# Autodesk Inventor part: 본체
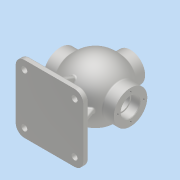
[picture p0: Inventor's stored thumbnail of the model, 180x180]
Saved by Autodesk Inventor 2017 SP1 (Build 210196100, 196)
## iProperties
Part Number: 본체
Material: 알루미늄 6061
Document SubType Name: Modeling
Designer: MRC
Density: 2.7 g/cm^3
Appearance: 알루미늄 - 평지
Mass: 1526.73 g
Surface Area: 1173.98 cm^2
Volume: 565.456 cm^3
Author: MRC
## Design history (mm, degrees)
sketch "스케치1"
  geometry: L1 (-65, 0)-(65, 0); L2 (-65, 0)-(-65, 31); L3 (-65, 31)-(-44.215, 31); L4 (65, 0)-(65, 31); L5 (65, 31)-(44.215, 31); L6 (-65, 17.5)-(-49, 17.5); L7 (-49, 17.5)-(-49, 15); L8 (-49, 15)-(-41.364, 15); L9 (65, 17.5)-(49, 17.5); L10 (49, 17.5)-(49, 15); L11 (49, 15)-(41.364, 15); A1 r 54 centre (0, 0) between (44.215, 31) and (-44.215, 31); A2 r 44 centre (0, 0) between (41.364, 15) and (-41.364, 15); 2 further points
  constraints: 22 end point, 5 perpendicular, 5 point on line, 4 point on circle, 3 coincident, 2 centre point, 2 horizontal, 2 vertical, 1 midpoint
  dimensions: "d0" = 130 distance of L1.start L1.end; "d1" = 108 diameter of A1; "d2" = 62 diameter of L5 L1; "d3" = 62 diameter of L3 L1; "d4" = 88 diameter of A2; "d5" = 35 diameter of L9 L1; "d6" = 16 distance of L9.start L9.end; "d7" = 16 distance of L6.start L6.end; "d8" = 30 diameter of L8 L1
revolve "회전1" sketch "스케치1" stored, may be unused: angle "d9" = 90 deg
chamfer "모따기1" distance "d10" = 1; stored, may be unused: second distance "d11" = 2, angle "d12" = 45 deg
chamfer "모따기2" distance "d13" = 1; stored, may be unused: second distance "d14" = 2, angle "d15" = 45 deg
fillet "모깎기1" dims "d16" = 0.6
node "작업 평면1"
sketch "스케치2"
  geometry: L1 (62.5, -62.5)-(-62.5, -62.5); L2 (-62.5, -62.5)-(-62.5, 62.5); L3 (-62.5, 62.5)-(62.5, 62.5); L4 (62.5, 62.5)-(62.5, -62.5); L5 (62.5, -62.5)-(-62.5, 62.5); L6 (-62.5, -62.5)-(62.5, 62.5); 1 further point
  constraints: 12 end point, 2 midpoint, 2 parallel, 2 perpendicular, 1 horizontal
  dimensions: "d18" = 125 distance of L2.end L3.end
sketch "스케치3"
  geometry: C1 r 31 at (0, 0) reference; 1 further point
  constraints: 1 vertical alignment
  dimensions: "d19" = 24 distance of point (0, 24) C1.centre
hole "구멍1" sketch "스케치3" at (0, 24) diameter "d20" = 3.242; stored, may be unused: countersink angle "d24" = 90 deg, drill point angle "d26" = 118 deg; dims "d21" = 12, "d22" = 4, "d23" = 2, "d25" = 15
node "작업 평면2"
sketch "스케치4"
  geometry: C1 r 27 at (0, 0); 1 further point
  constraints: 1 centre point, 1 coincident
  dimensions: "d31" = 54 diameter of C1
extrude "돌출1" join sketch "스케치4" stored distance "d32" = 10; taper "d33" = 0 deg
sketch "스케치5"
  geometry: C1 r 27 at (0, 0) reference; C2 r 13 at (0, 0)
  constraints: 1 centre point, 1 coincident
  dimensions: "d34" = 26 diameter of C2
extrude "돌출2" cut sketch "스케치5" stored distance "d35" = 0; taper "d36" = 0 deg
sketch "스케치6"
  geometry: C1 r 13 at (0, 0) reference; 1 further point
  constraints: 1 vertical alignment
  dimensions: "d37" = 20 distance of C1.centre point (0, 20)
hole "구멍2" sketch "스케치6" at (0, 20) diameter "d38" = 3.242; stored, may be unused: countersink angle "d42" = 90 deg, drill point angle "d44" = 118 deg; dims "d39" = 9, "d40" = 4, "d41" = 2, "d43" = 11
extrude "돌출3" join sketch "스케치2" distance "d48" = 10; taper "d49" = 0 deg
fillet "모깎기2" dims "d50" = 16
fillet "모깎기3" dims "d51" = 3
sketch "스케치7"
  geometry: L1 (-75, -50.5)-(-50.777, -41.684); L2 (-75, 50.5)-(-58.826, 44.613); L3 (-78, -62.5)-(-85, -62.5) reference; L4 (-75, 46.5)-(-75, -46.5) reference; L5 (-85, 62.5)-(-78, 62.5) reference; 1 further point
  constraints: 4 end point, 2 point on line
  dimensions: "d52" = 20 deg angle of L1 L3; "d53" = 12 distance from line of L1.start L3; "d54" = 20 deg angle of L2 L5; "d55" = 12 distance from line of L2.start L5
feature "리브1" dims "d56" = 30, "d57" = 8, "d58" = 0, "d59" = 0, "d60" = 1, "d61" = 1
feature "리브2" dims "d62" = 30, "d63" = 8, "d64" = 0, "d65" = 0, "d66" = 1, "d67" = 1
sketch "스케치8"
  geometry: L1 (50.5, -75)-(43.286, -55.179); L2 (-50.5, -75)-(-43.704, -56.329); L3 (62.5, -85)-(62.5, -78) reference; L4 (-62.5, -78)-(-62.5, -85) reference; L5 (46.5, -75)-(-46.5, -75) reference; 1 further point
  constraints: 4 end point, 2 point on line
  dimensions: "d68" = 12 distance from line of L1.start L3; "d69" = 20 deg angle of L3 L1; "d70" = 20 deg angle of L2 L4; "d71" = 12 distance from line of L4 L2.start
feature "리브3" dims "d72" = 30, "d73" = 8, "d74" = 0, "d75" = 0, "d76" = 1, "d77" = 1
feature "리브4" dims "d78" = 30, "d79" = 8, "d80" = 0, "d81" = 0, "d82" = 1, "d83" = 1
fillet "모깎기4" dims "d84" = 3
fillet "모깎기5" dims "d85" = 3
fillet "모깎기6" dims "d86" = 3
chamfer "모따기3" distance "d87" = 1; stored, may be unused: second distance "d88" = 2, angle "d89" = 45 deg
fillet "모깎기7" dims "d90" = 3
node "작업 평면3"
sketch "스케치9"
  geometry: L1 (-27, 65)-(27, 65) reference; 2 further points
  constraints: 1 vertical alignment, 1 other
  dimensions: "d92" = 9 distance from line of point (0, 56) L1
feature "엠보싱1" sketch "스케치9" dims "d0" = 130, "d93" = 0.5, "d94" = 0
sketch "스케치10"
  geometry: C1 r 5.5 at (-46.5, -46.5); C2 r 5.5 at (-46.5, 46.5); C3 r 5.5 at (46.5, 46.5); C4 r 5.5 at (46.5, -46.5); A1 r 13 centre (46.5, 46.5) between (59.5, 46.5) and (46.5, 59.5) reference; A2 r 13 centre (-46.5, 46.5) between (-46.5, 59.5) and (-59.5, 46.5) reference; A3 r 13 centre (-46.5, -46.5) between (-59.5, -46.5) and (-46.5, -59.5) reference; A4 r 13 centre (46.5, -46.5) between (46.5, -59.5) and (59.5, -46.5) reference; 1 further point
  constraints: 4 centre point, 4 coincident
  dimensions: "d95" = 11 diameter of C1; "d96" = 11 diameter of C2; "d97" = 11 diameter of C3; "d98" = 11 diameter of C4
extrude "돌출4" cut sketch "스케치10" stored distance "d99" = 10; taper "d100" = 0 deg
node "솔리드1"
pattern_circular "원형 패턴1" dims angle "d28" = 360 deg
mirror "미러1"
pattern_circular "원형 패턴2" dims angle "d46" = 360 deg
other parameters: "d17" = -85, "d30" = 65, "d91" = -59.75
